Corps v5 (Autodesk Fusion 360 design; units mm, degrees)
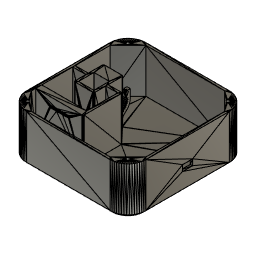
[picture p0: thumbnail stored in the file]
base_feature "Fonction de base" bodies "Corps de maillage1"
scale "Echelle" ScaleFactor 0.1
sketch "Esquisse2" plane through (0, 0, -410) normal (0, 0, 1) x axis (-1, 0, 0)
  line L1 (-774.7, -938.35) -> (-762, -938.35)
  line L2 (-761, -948.35) -> (-774.7, -938.35)
  line L3 (-762, -938.35) -> (-761, -948.35)
  line L4 (-774.7, -938.35) -> (-774.7, -925.65)
  line L5 (-774.7, -925.65) -> (-762, -925.65)
  line L6 (-762, -938.35) -> (-762, -925.65)
  line L7 (-774.7, -938.55) -> (-762, -938.55)
  line L8 (-762, -938.55) -> (-762, -938.35)
  line L9 (-774.7, -938.55) -> (-774.7, -938.35)
  line L10 (-774.8, -938.35) -> (-774.8, -925.55)
  line L11 (-774.8, -925.55) -> (-761.9, -925.55)
  line L12 (-761.9, -938.35) -> (-761.9, -925.55)
  line L13 (-774.8, -938.55) -> (-774.7, -938.55)
  line L14 (-774.8, -938.55) -> (-774.8, -938.35)
  line L15 (-761.9, -938.55) -> (-762, -938.55)
  line L16 (-761.9, -938.35) -> (-761.9, -938.55)
  point P8 (-762, -938.35)
  point P11 (-762, -938.35)
  point P6 (-774.7, -938.35)
  point P12 (-774.7, -938.35)
  horizontal L7
  coincident P8 P11
  coincident P6 P12
  vertical L9
  vertical L8
  perpendicular L9 L13
  perpendicular L13 L14
  perpendicular L15 L16
  dimension "d4" distance L5 L7 = 12.9
  dimension "d18" = 0.1
extrude "Extrusion1" cut sketch "Esquisse2" to an object
sketch "Esquisse3" plane through (0, 0, -441) normal (0, 0, 1) x axis (-1, 0, 0)
  line L1 (-783.5, -920.65) -> (-781.5, -918.65)
  line L2 (-776.5, -920.65) -> (-783.5, -920.65)
  line L3 (-781.5, -918.65) -> (-776.5, -920.65)
  line L4 (-783.5, -920.65) -> (-776.5, -920.65)
  line L5 (-776.5, -920.65) -> (-776.5, -918.65)
  line L6 (-781.5, -918.65) -> (-776.5, -918.65)
  line L7 (-781.5, -918.65) -> (-781.5, -916.85)
  line L8 (-781.5, -916.85) -> (-776.5, -916.85)
  line L9 (-776.5, -916.85) -> (-776.5, -914.85)
  line L10 (-783.5, -914.85) -> (-776.5, -914.85)
  line L11 (-783.5, -920.65) -> (-783.5, -914.85)
  line L12 (-760.2, -920.65) -> (-760.2, -918.65)
  line L13 (-760.2, -920.65) -> (-753.2, -920.65)
  line L14 (-753.2, -920.65) -> (-753.2, -914.85)
  line L15 (-760.2, -914.85) -> (-753.2, -914.85)
  line L16 (-760.2, -916.85) -> (-760.2, -914.85)
  line L17 (-760.2, -916.85) -> (-755.2, -916.85)
  line L18 (-755.2, -918.65) -> (-755.2, -916.85)
  line L19 (-760.2, -918.65) -> (-755.2, -918.65)
extrude "Extrusion2" add sketch "Esquisse3" along normal blind 4
sketch "Esquisse4" plane through (0, 0, -444) normal (0, 0, 1) x axis (-1, 0, 0)
  line L1 (-760.2, -920.65) -> (-776.5, -920.65)
  line L2 (-776.5, -918.65) -> (-760.2, -920.65)
  line L3 (-776.5, -920.65) -> (-776.5, -918.65)
  line L4 (-776.5, -920.65) -> (-760.2, -920.65)
  line L5 (-776.5, -918.65) -> (-760.2, -918.65)
  line L6 (-776.5, -916.85) -> (-760.2, -916.85)
  line L7 (-776.5, -914.85) -> (-760.2, -914.85)
  line L8 (-760.2, -916.85) -> (-760.2, -914.85)
  line L9 (-760.2, -920.65) -> (-760.2, -918.65)
  line L10 (-776.5, -918.65) -> (-776.5, -920.65)
  line L11 (-776.5, -914.85) -> (-776.5, -916.85)
extrude "Extrusion3" add sketch "Esquisse4" along normal blind 4
sketch "Esquisse5" plane through (0, 0, -447) normal (0, 0, 1) x axis (-1, 0, 0)
  line L1 (-755.2, -918.65) -> (-781.5, -918.65)
  line L2 (-781.5, -916.85) -> (-755.2, -918.65)
  line L3 (-781.5, -918.65) -> (-781.5, -916.85)
  line L4 (-776.5, -918.65) -> (-760.2, -918.65)
  line L5 (-755.2, -918.65) -> (-781.5, -916.85)
  line L6 (-755.2, -916.85) -> (-755.2, -918.65)
  line L7 (-781.5, -916.85) -> (-755.2, -916.85)
extrude "Extrusion4" add sketch "Esquisse5" along normal blind 4
align "Aligner1"
align "Aligner2"
align "Aligner3"
move "Déplacer"
sketch "Esquisse6" plane through (0, 0, 39) normal (0, 0, 1) x axis (-1, 0, 0)
  line L1 (41.134, 42.5) -> (33, 48)
  line L2 (38.1187, 49.6722) -> (41.134, 42.5)
  line L3 (33, 48) -> (38.1187, 49.6722)
  circle C1 centre (41.9941, 42) radius 0.9941
  circle C2 centre (41.9941, 42) radius 1.25
  concentric C1 C2
  dimension "d13" diameter C2 = 2.5
extrude "Extrusion5" cut sketch "Esquisse6" profile of L1 L2 C2 against normal blind 12
circular_pattern "Réseau C" TotalAngle 360
sketch "Esquisse7" plane through (-23, 0, 0) normal (1, 0, 0) x axis (0, 1, 0)
  line L1 (21.4211, 19.0416) -> (23.4211, 23.0711)
  line L2 (23.4211, 18.2132) -> (21.4211, 19.0416)
  line L3 (23.4211, 23.0711) -> (23.4211, 18.2132)
  line L4 (24.9211, 24.0711) -> (23.4211, 24.0711)
  line L5 (24.9211, 17.0663) -> (24.9211, 24.0711)
  line L6 (22.4211, 24.0711) -> (23.4211, 24.0711)
  line L7 (22.4211, 18.5336) -> (22.4211, 24.0711)
  line L8 (16.35, 4.7414) -> (16.35, 2)
  line L9 (17.85, 2.0027) -> (16.35, 2)
  line L10 (22.4211, 26.0414) -> (22.4211, 24.0711)
  arc A1 centre (15.1365, 17.0663) radius 9.7846 clockwise from (24.9211, 17.0663) to (21.0373, 9.2613)
  arc A2 centre (25.9366, 2.7809) radius 8.124 clockwise from (17.85, 2.0027) to (21.0373, 9.2613)
  arc A3 centre (12.6551, 18.5336) radius 9.7659 clockwise from (22.4211, 18.5336) to (19.2509, 11.3316)
  arc A4 centre (25.2863, 4.7414) radius 8.9363 clockwise from (16.35, 4.7414) to (19.2509, 11.3316)
  point P5 (23.4211, 24.0711)
  point P6 (23.4211, 24.0711)
  point P17 (16.35, 2)
  point P18 (16.35, 2)
  point P7 (24.9211, 24.0711)
  point P13 (22.4211, 24.0711)
  point P11 (17.85, 2.0027)
  coincident P5 P6
  horizontal L4
  perpendicular L4 L5
  tangent L5 A1
  tangent A1 A2
  parallel L4 L6
  tangent L7 A3
  coincident P17 P18
  vertical L8
  vertical L10
  vertical L7
  tangent A3 A4
  tangent L8 A4
  dimension "d19" distance P6 P7 = 1.5
  dimension "d20" distance P6 P13 = 1
  dimension "d21" distance P11 P17 = 1.5
extrude "Extrusion6" add sketch "Esquisse7" profile of L1 L2 L3 L4 L5 A1 A2 L6 L7 A3 L8 L9 A4 against normal blind 3
sketch "Esquisse8" plane through (0, 0, 0) normal (0, 0, -1) x axis (1, 0, 0)
  line L1 (1.4208, -33.3801) -> (35, 48)
  line L2 (15.3097, -31.8449) -> (1.4208, -33.3801)
  line L3 (35, 48) -> (15.3097, -31.8449)
  line L4 (43, -30.4361) -> (-42, -30.4361)
  line L5 (43, -41) -> (43, -30.4361)
  line L6 (-42, -41) -> (43, -41)
  line L7 (-42, -30.4361) -> (-42, -41)
  horizontal L4
  vertical L5
  horizontal L6
  vertical L7
extrude "Extrusion7" add sketch "Esquisse8" to an object
named bodies: "Corps de maillage1"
